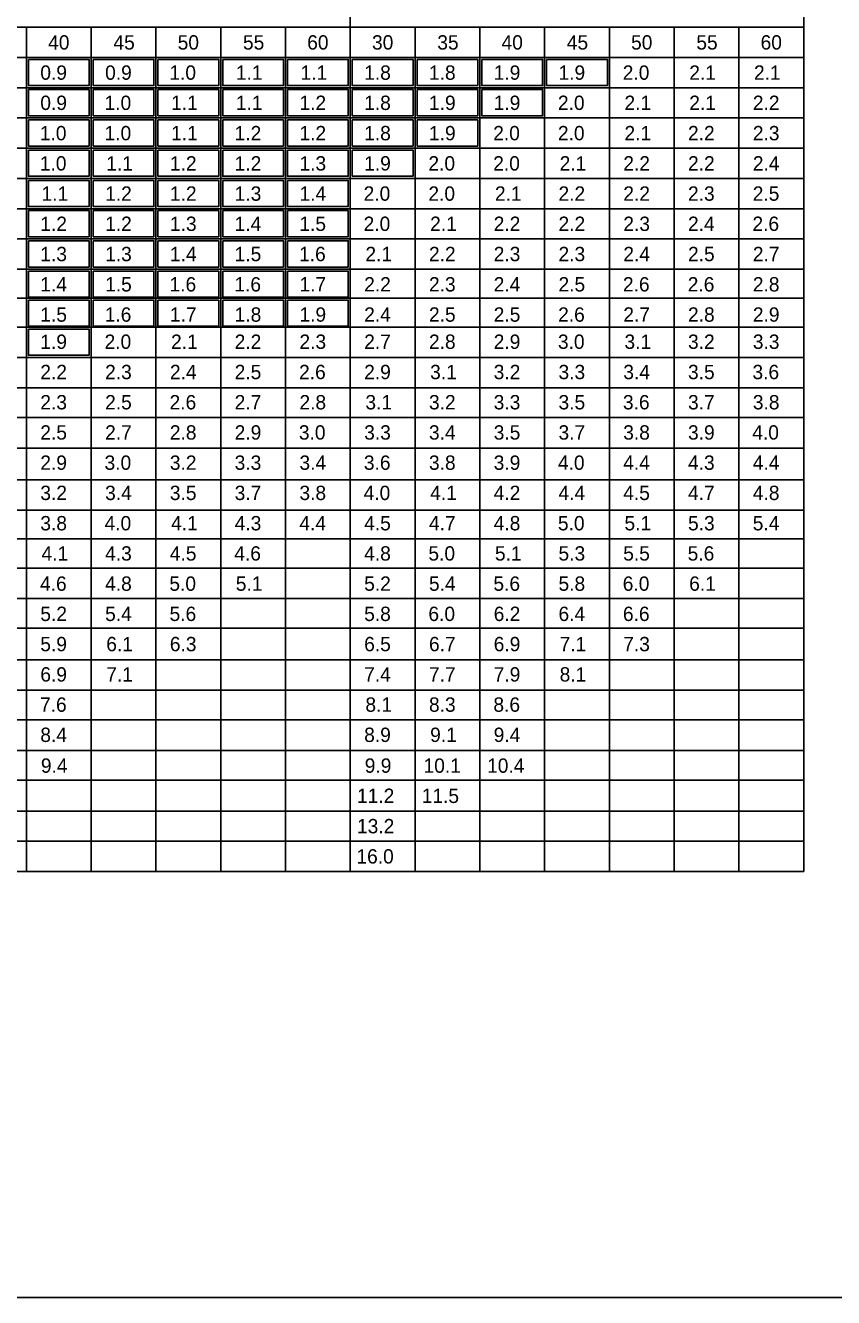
# Model space of a CAD drawing. Extents: x -439.1 to -407.9, y -458.1 to -437.7.
# Drawn here: x -430.26 to -421.8, y -458.05 to -444.75 of the extents above; entities that cross this region are included whole.
import ezdxf

# ---------------------------------------------------------------- set-up
doc = ezdxf.new("R2010")
doc.units = 0
for name, color, linetype in [('Bridge-Named Boundary', 7, 'Continuous'), ('Common-Notes', 7, 'Continuous'), ('Level 4', 7, 'Continuous')]:
    doc.layers.add(name, color=color, linetype=linetype)

msp = doc.modelspace()

# ---------------------------------------------------------------- linework, layer by layer
at = {"layer": 'Bridge-Named Boundary'}
msp.add_lwpolyline([(-439.109, -458.051), (-407.859, -458.051), (-407.859, -437.676), (-439.109, -437.676)], close=True, dxfattribs=at)
at = {"layer": 'Level 4'}
for p, q in [((-422.115, -443.186), (-422.115, -453.595)), ((-426.858, -444.134), (-426.858, -453.595)), ((-436.344, -444.767), (-422.115, -444.767)), ((-430.246, -444.767), (-430.246, -453.595)), ((-429.568, -444.767), (-429.568, -453.595)), ((-428.891, -444.767), (-428.891, -453.595)), ((-428.213, -444.767), (-428.213, -453.595)), ((-427.536, -444.767), (-427.536, -453.595)), ((-426.18, -444.767), (-426.18, -453.595)), ((-425.503, -444.767), (-425.503, -453.595)), ((-424.825, -444.767), (-424.825, -453.595)), ((-424.148, -444.767), (-424.148, -453.595)), ((-423.47, -444.767), (-423.47, -453.595)), ((-422.793, -444.767), (-422.793, -453.595)), ((-437.38, -445.083), (-422.115, -445.083)), ((-437.38, -445.399), (-422.115, -445.399)), ((-437.38, -445.715), (-422.115, -445.715)), ((-437.38, -446.032), (-422.115, -446.032)), ((-437.38, -446.348), (-422.115, -446.348)), ((-437.38, -446.664), (-422.115, -446.664)), ((-437.38, -446.98), (-422.115, -446.98)), ((-437.38, -447.296), (-422.115, -447.296)), ((-437.38, -447.6), (-422.115, -447.6)), ((-437.38, -447.903), (-422.115, -447.903)), ((-437.38, -448.22), (-422.115, -448.22)), ((-437.38, -448.536), (-422.115, -448.536)), ((-437.38, -448.847), (-422.115, -448.847)), ((-437.38, -449.168), (-422.115, -449.168)), ((-437.38, -449.5), (-422.115, -449.5)), ((-437.38, -449.816), (-422.115, -449.816)), ((-437.38, -450.117), (-422.115, -450.117)), ((-437.38, -450.422), (-422.115, -450.422)), ((-437.38, -450.739), (-422.115, -450.739)), ((-437.38, -451.05), (-422.115, -451.05)), ((-437.38, -451.382), (-422.115, -451.382)), ((-437.38, -451.698), (-422.115, -451.698)), ((-437.38, -452.009), (-422.115, -452.009)), ((-437.38, -452.33), (-422.115, -452.33)), ((-437.38, -452.64), (-422.115, -452.64)), ((-437.38, -452.963), (-422.115, -452.963)), ((-437.38, -453.279), (-422.115, -453.279)), ((-437.38, -453.595), (-422.115, -453.595))]:
    msp.add_line(p, q, dxfattribs=at)
for points in [[(-430.226, -445.103), (-429.59, -445.103), (-429.59, -445.377), (-430.226, -445.377)], [(-429.548, -445.103), (-428.912, -445.103), (-428.912, -445.377), (-429.548, -445.377)], [(-428.871, -445.103), (-428.235, -445.103), (-428.235, -445.377), (-428.871, -445.377)], [(-428.193, -445.103), (-427.557, -445.103), (-427.557, -445.377), (-428.193, -445.377)], [(-427.516, -445.103), (-426.88, -445.103), (-426.88, -445.377), (-427.516, -445.377)], [(-426.838, -445.103), (-426.202, -445.103), (-426.202, -445.377), (-426.838, -445.377)], [(-426.16, -445.103), (-425.525, -445.103), (-425.525, -445.377), (-426.16, -445.377)], [(-425.483, -445.103), (-424.847, -445.103), (-424.847, -445.377), (-425.483, -445.377)], [(-424.805, -445.103), (-424.169, -445.103), (-424.169, -445.377), (-424.805, -445.377)], [(-430.226, -445.419), (-429.59, -445.419), (-429.59, -445.693), (-430.226, -445.693)], [(-429.548, -445.419), (-428.912, -445.419), (-428.912, -445.693), (-429.548, -445.693)], [(-428.871, -445.419), (-428.235, -445.419), (-428.235, -445.693), (-428.871, -445.693)], [(-428.193, -445.419), (-427.557, -445.419), (-427.557, -445.693), (-428.193, -445.693)], [(-427.516, -445.419), (-426.88, -445.419), (-426.88, -445.693), (-427.516, -445.693)], [(-426.838, -445.419), (-426.202, -445.419), (-426.202, -445.693), (-426.838, -445.693)], [(-426.16, -445.419), (-425.525, -445.419), (-425.525, -445.693), (-426.16, -445.693)], [(-425.483, -445.419), (-424.847, -445.419), (-424.847, -445.693), (-425.483, -445.693)], [(-430.226, -445.735), (-429.59, -445.735), (-429.59, -446.009), (-430.226, -446.009)], [(-429.548, -445.735), (-428.912, -445.735), (-428.912, -446.009), (-429.548, -446.009)], [(-428.871, -445.735), (-428.235, -445.735), (-428.235, -446.009), (-428.871, -446.009)], [(-428.193, -445.735), (-427.557, -445.735), (-427.557, -446.009), (-428.193, -446.009)], [(-427.516, -445.735), (-426.88, -445.735), (-426.88, -446.009), (-427.516, -446.009)], [(-426.838, -445.735), (-426.202, -445.735), (-426.202, -446.009), (-426.838, -446.009)], [(-426.16, -445.735), (-425.525, -445.735), (-425.525, -446.009), (-426.16, -446.009)], [(-430.226, -446.052), (-429.59, -446.052), (-429.59, -446.325), (-430.226, -446.325)], [(-429.548, -446.052), (-428.912, -446.052), (-428.912, -446.325), (-429.548, -446.325)], [(-428.871, -446.052), (-428.235, -446.052), (-428.235, -446.325), (-428.871, -446.325)], [(-428.193, -446.052), (-427.557, -446.052), (-427.557, -446.325), (-428.193, -446.325)], [(-427.516, -446.052), (-426.88, -446.052), (-426.88, -446.325), (-427.516, -446.325)], [(-426.838, -446.052), (-426.202, -446.052), (-426.202, -446.325), (-426.838, -446.325)], [(-430.226, -446.368), (-429.59, -446.368), (-429.59, -446.642), (-430.226, -446.642)], [(-429.548, -446.368), (-428.912, -446.368), (-428.912, -446.642), (-429.548, -446.642)], [(-428.871, -446.368), (-428.235, -446.368), (-428.235, -446.642), (-428.871, -446.642)], [(-428.193, -446.368), (-427.557, -446.368), (-427.557, -446.642), (-428.193, -446.642)], [(-427.516, -446.368), (-426.88, -446.368), (-426.88, -446.642), (-427.516, -446.642)], [(-430.226, -446.684), (-429.59, -446.684), (-429.59, -446.958), (-430.226, -446.958)], [(-429.548, -446.684), (-428.912, -446.684), (-428.912, -446.958), (-429.548, -446.958)], [(-428.871, -446.684), (-428.235, -446.684), (-428.235, -446.958), (-428.871, -446.958)], [(-428.193, -446.684), (-427.557, -446.684), (-427.557, -446.958), (-428.193, -446.958)], [(-427.516, -446.684), (-426.88, -446.684), (-426.88, -446.958), (-427.516, -446.958)], [(-430.226, -447), (-429.59, -447), (-429.59, -447.274), (-430.226, -447.274)], [(-429.548, -447), (-428.912, -447), (-428.912, -447.274), (-429.548, -447.274)], [(-428.871, -447), (-428.235, -447), (-428.235, -447.274), (-428.871, -447.274)], [(-428.193, -447), (-427.557, -447), (-427.557, -447.274), (-428.193, -447.274)], [(-427.516, -447), (-426.88, -447), (-426.88, -447.274), (-427.516, -447.274)], [(-430.226, -447.316), (-429.59, -447.316), (-429.59, -447.59), (-430.226, -447.59)], [(-429.548, -447.316), (-428.912, -447.316), (-428.912, -447.59), (-429.548, -447.59)], [(-428.871, -447.316), (-428.235, -447.316), (-428.235, -447.59), (-428.871, -447.59)], [(-428.193, -447.316), (-427.557, -447.316), (-427.557, -447.59), (-428.193, -447.59)], [(-427.516, -447.316), (-426.88, -447.316), (-426.88, -447.59), (-427.516, -447.59)], [(-430.226, -447.62), (-429.59, -447.62), (-429.59, -447.894), (-430.226, -447.894)], [(-429.548, -447.62), (-428.912, -447.62), (-428.912, -447.894), (-429.548, -447.894)], [(-428.871, -447.62), (-428.235, -447.62), (-428.235, -447.894), (-428.871, -447.894)], [(-428.193, -447.62), (-427.557, -447.62), (-427.557, -447.894), (-428.193, -447.894)], [(-427.516, -447.62), (-426.88, -447.62), (-426.88, -447.894), (-427.516, -447.894)], [(-430.226, -447.923), (-429.59, -447.923), (-429.59, -448.197), (-430.226, -448.197)]]:
    msp.add_lwpolyline(points, close=True, dxfattribs=at)

# ---------------------------------------------------------------- texts
at = {"layer": 'Common-Notes'}
for s, p in [('40', (-430.019, -445)), ('45', (-429.336, -445)), ('50', (-428.664, -445)), ('55', (-427.981, -445)), ('60', (-427.309, -445)), ('30', (-426.631, -445)), ('35', (-425.948, -445)), ('40', (-425.276, -445)), ('45', (-424.593, -445)), ('50', (-423.921, -445)), ('55', (-423.238, -445)), ('60', (-422.566, -445)), ('0.9', (-430.101, -445.316)), ('0.9', (-429.423, -445.316)), ('1.0', (-428.751, -445.316)), ('1.1', (-428.055, -445.316)), ('1.1', (-427.378, -445.316)), ('1.8', (-426.713, -445.316)), ('1.8', (-426.035, -445.316)), ('1.9', (-425.358, -445.316)), ('1.9', (-424.68, -445.316)), ('2.0', (-424.008, -445.316)), ('2.1', (-423.312, -445.316)), ('2.1', (-422.635, -445.316)), ('0.9', (-430.101, -445.632)), ('1.0', (-429.429, -445.632)), ('1.1', (-428.733, -445.632)), ('1.1', (-428.055, -445.632)), ('1.2', (-427.39, -445.632)), ('1.8', (-426.713, -445.632)), ('1.9', (-426.035, -445.632)), ('1.9', (-425.358, -445.632)), ('2.0', (-424.686, -445.632)), ('2.1', (-423.99, -445.632)), ('2.1', (-423.312, -445.632)), ('2.2', (-422.647, -445.632)), ('1.0', (-430.106, -445.949)), ('1.0', (-429.429, -445.949)), ('1.1', (-428.733, -445.949)), ('1.2', (-428.068, -445.949)), ('1.2', (-427.39, -445.949)), ('1.8', (-426.713, -445.949)), ('1.9', (-426.035, -445.949)), ('2.0', (-425.363, -445.949)), ('2.0', (-424.686, -445.949)), ('2.1', (-423.99, -445.949)), ('2.2', (-423.325, -445.949)), ('2.3', (-422.647, -445.949)), ('1.0', (-430.106, -446.265)), ('1.1', (-429.411, -446.265)), ('1.2', (-428.745, -446.265)), ('1.2', (-428.068, -446.265)), ('1.3', (-427.39, -446.265)), ('1.9', (-426.713, -446.265)), ('2.0', (-426.041, -446.265)), ('2.0', (-425.363, -446.265)), ('2.1', (-424.668, -446.265)), ('2.2', (-424.002, -446.265)), ('2.2', (-423.325, -446.265)), ('2.4', (-422.647, -446.265)), ('1.1', (-430.088, -446.581)), ('1.2', (-429.423, -446.581)), ('1.2', (-428.745, -446.581)), ('1.3', (-428.068, -446.581)), ('1.4', (-427.39, -446.581)), ('2.0', (-426.719, -446.581)), ('2.0', (-426.041, -446.581)), ('2.1', (-425.345, -446.581)), ('2.2', (-424.68, -446.581)), ('2.2', (-424.002, -446.581)), ('2.3', (-423.325, -446.581)), ('2.5', (-422.648, -446.581)), ('1.2', (-430.101, -446.897)), ('1.2', (-429.423, -446.897)), ('1.3', (-428.745, -446.897)), ('1.4', (-428.068, -446.897)), ('1.5', (-427.391, -446.897)), ('2.0', (-426.719, -446.897)), ('2.1', (-426.023, -446.897)), ('2.2', (-425.358, -446.897)), ('2.2', (-424.68, -446.897)), ('2.3', (-424.002, -446.897)), ('2.4', (-423.325, -446.897)), ('2.6', (-422.651, -446.897)), ('1.3', (-430.101, -447.213)), ('1.3', (-429.423, -447.213)), ('1.4', (-428.745, -447.213)), ('1.5', (-428.068, -447.213)), ('1.6', (-427.394, -447.213)), ('2.1', (-426.7, -447.213)), ('2.2', (-426.035, -447.213)), ('2.3', (-425.358, -447.213)), ('2.3', (-424.68, -447.213)), ('2.4', (-424.002, -447.213)), ('2.5', (-423.325, -447.213)), ('2.7', (-422.647, -447.213)), ('1.4', (-430.101, -447.53)), ('1.5', (-429.423, -447.53)), ('1.6', (-428.749, -447.53)), ('1.6', (-428.071, -447.53)), ('1.7', (-427.39, -447.53)), ('2.2', (-426.713, -447.53)), ('2.3', (-426.035, -447.53)), ('2.4', (-425.358, -447.53)), ('2.5', (-424.68, -447.53)), ('2.6', (-424.006, -447.53)), ('2.6', (-423.328, -447.53)), ('2.8', (-422.647, -447.53)), ('1.5', (-430.101, -447.846)), ('1.6', (-429.427, -447.846)), ('1.7', (-428.745, -447.846)), ('1.8', (-428.068, -447.846)), ('1.9', (-427.39, -447.846)), ('2.4', (-426.713, -447.846)), ('2.5', (-426.035, -447.846)), ('2.5', (-425.358, -447.846)), ('2.6', (-424.684, -447.846)), ('2.7', (-424.002, -447.846)), ('2.8', (-423.325, -447.846)), ('2.9', (-422.647, -447.846)), ('1.9', (-430.101, -448.13)), ('2.0', (-429.429, -448.13)), ('2.1', (-428.733, -448.13)), ('2.2', (-428.068, -448.13)), ('2.3', (-427.39, -448.13)), ('2.7', (-426.713, -448.13)), ('2.8', (-426.035, -448.13)), ('2.9', (-425.358, -448.13)), ('3.0', (-424.686, -448.13)), ('3.1', (-423.99, -448.13)), ('3.2', (-423.325, -448.13)), ('3.3', (-422.647, -448.13)), ('2.2', (-430.101, -448.447)), ('2.3', (-429.423, -448.447)), ('2.4', (-428.745, -448.447)), ('2.5', (-428.068, -448.447)), ('2.6', (-427.394, -448.447)), ('2.9', (-426.713, -448.447)), ('3.1', (-426.023, -448.447)), ('3.2', (-425.358, -448.447)), ('3.3', (-424.68, -448.447)), ('3.4', (-424.002, -448.447)), ('3.5', (-423.325, -448.447)), ('3.6', (-422.651, -448.447)), ('2.3', (-430.101, -448.763)), ('2.5', (-429.423, -448.763)), ('2.6', (-428.749, -448.763)), ('2.7', (-428.068, -448.763)), ('2.8', (-427.39, -448.763)), ('3.1', (-426.7, -448.763)), ('3.2', (-426.035, -448.763)), ('3.3', (-425.358, -448.763)), ('3.5', (-424.68, -448.763)), ('3.6', (-424.006, -448.763)), ('3.7', (-423.325, -448.763)), ('3.8', (-422.647, -448.763)), ('2.5', (-430.101, -449.079)), ('2.7', (-429.423, -449.079)), ('2.8', (-428.746, -449.079)), ('2.9', (-428.068, -449.079)), ('3.0', (-427.396, -449.079)), ('3.3', (-426.713, -449.079)), ('3.4', (-426.035, -449.079)), ('3.5', (-425.358, -449.079)), ('3.7', (-424.68, -449.079)), ('3.8', (-424.003, -449.079)), ('3.9', (-423.325, -449.079)), ('4.0', (-422.653, -449.079)), ('2.9', (-430.101, -449.395)), ('3.0', (-429.429, -449.395)), ('3.2', (-428.746, -449.395)), ('3.3', (-428.068, -449.395)), ('3.4', (-427.39, -449.395)), ('3.6', (-426.716, -449.395)), ('3.8', (-426.035, -449.395)), ('3.9', (-425.358, -449.395)), ('4.0', (-424.686, -449.395)), ('4.4', (-424.003, -449.395)), ('4.3', (-423.325, -449.395)), ('4.4', (-422.647, -449.395)), ('3.2', (-430.101, -449.711)), ('3.4', (-429.423, -449.711)), ('3.5', (-428.746, -449.711)), ('3.7', (-428.068, -449.711)), ('3.8', (-427.39, -449.711)), ('4.0', (-426.719, -449.711)), ('4.1', (-426.023, -449.711)), ('4.2', (-425.358, -449.711)), ('4.4', (-424.68, -449.711)), ('4.5', (-424.003, -449.711)), ('4.7', (-423.325, -449.711)), ('4.8', (-422.647, -449.711)), ('3.8', (-430.101, -450.028)), ('4.0', (-429.429, -450.028)), ('4.1', (-428.733, -450.028)), ('4.3', (-428.068, -450.028)), ('4.4', (-427.391, -450.028)), ('4.5', (-426.713, -450.028)), ('4.7', (-426.035, -450.028)), ('4.8', (-425.358, -450.028)), ('5.0', (-424.686, -450.028)), ('5.1', (-423.99, -450.028)), ('5.3', (-423.325, -450.028)), ('5.4', (-422.648, -450.028)), ('4.1', (-430.088, -450.344)), ('4.3', (-429.423, -450.344)), ('4.5', (-428.746, -450.344)), ('4.6', (-428.072, -450.344)), ('4.8', (-426.713, -450.344)), ('5.0', (-426.041, -450.344)), ('5.1', (-425.345, -450.344)), ('5.3', (-424.68, -450.344)), ('5.5', (-424.003, -450.344)), ('5.6', (-423.329, -450.344)), ('4.6', (-430.104, -450.66)), ('4.8', (-429.423, -450.66)), ('5.0', (-428.751, -450.66)), ('5.1', (-428.056, -450.66)), ('5.2', (-426.713, -450.66)), ('5.4', (-426.035, -450.66)), ('5.6', (-425.361, -450.66)), ('5.8', (-424.68, -450.66)), ('6.0', (-424.008, -450.66)), ('6.1', (-423.313, -450.66)), ('5.2', (-430.101, -450.976)), ('5.4', (-429.423, -450.976)), ('5.6', (-428.749, -450.976)), ('5.8', (-426.713, -450.976)), ('6.0', (-426.041, -450.976)), ('6.2', (-425.358, -450.976)), ('6.4', (-424.68, -450.976)), ('6.6', (-424.006, -450.976)), ('5.9', (-430.101, -451.292)), ('6.1', (-429.411, -451.292)), ('6.3', (-428.746, -451.292)), ('6.5', (-426.713, -451.292)), ('6.7', (-426.035, -451.292)), ('6.9', (-425.358, -451.292)), ('7.1', (-424.668, -451.292)), ('7.3', (-424.003, -451.292)), ('6.9', (-430.101, -451.609)), ('7.1', (-429.411, -451.609)), ('7.4', (-426.713, -451.609)), ('7.7', (-426.035, -451.609)), ('7.9', (-425.358, -451.609)), ('8.1', (-424.668, -451.609)), ('7.6', (-430.104, -451.925)), ('8.1', (-426.7, -451.925)), ('8.3', (-426.035, -451.925)), ('8.6', (-425.361, -451.925)), ('8.4', (-430.101, -452.241)), ('8.9', (-426.713, -452.241)), ('9.1', (-426.023, -452.241)), ('9.4', (-425.358, -452.241)), ('9.4', (-430.095, -452.563)), ('9.9', (-426.707, -452.563)), ('10.1', (-426.092, -452.563)), ('10.4', (-425.427, -452.563)), ('11.2', (-426.788, -452.879)), ('11.5', (-426.111, -452.879)), ('13.2', (-426.788, -453.196)), ('16.0', (-426.794, -453.512))]:
    msp.add_text(s, height=0.15, dxfattribs=at).set_placement(p)

doc.saveas('drawing.dxf')
